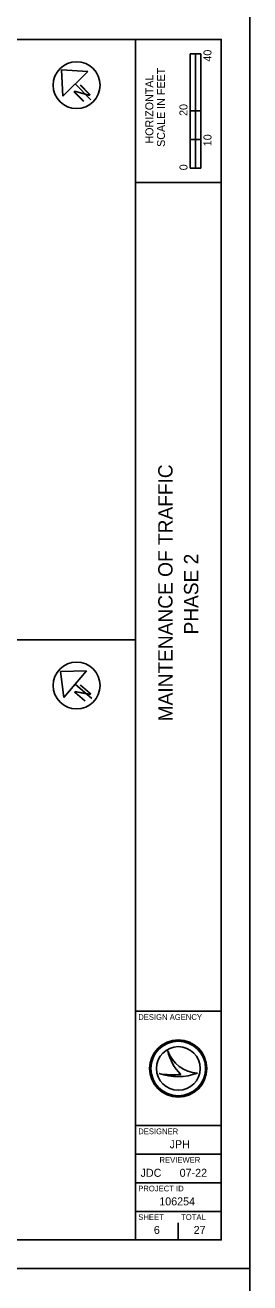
# Model space of a CAD drawing. Extents: x 0 to 5770, y -1320 to 440.
# Drawn here: x 601.5 to 680, y -445 to -5 of the extents above; entities that cross this region are included whole.
import ezdxf

# ---------------------------------------------------------------- set-up
doc = ezdxf.new("R2010")
doc.units = 0
for name, color, linetype in [('_CIVIL_CONSTRUCTION', 7, 'Continuous'), ('GE_P_Alignment', 7, 'Continuous'), ('GE_P_Alignment_100_Bearings', 7, 'Continuous'), ('GE_P_Alignment_100_Cardinal_Points', 7, 'Continuous'), ('HY_X_Water_Edge', 7, 'Continuous')]:
    doc.layers.add(name, color=color, linetype=linetype)

msp = doc.modelspace()

# ---------------------------------------------------------------- linework, layer by layer
at = {"layer": '_CIVIL_CONSTRUCTION'}
for points in [[(0, -440), (680, -440), (680, 0), (0, 0)], [(0, -880), (680, -880), (680, -440), (0, -440)]]:
    msp.add_lwpolyline(points, close=True, dxfattribs=at)
at = {"layer": 'GE_P_Alignment'}
for p, q in [((640, -430), (640, -10)), ((640, -60), (670, -60)), ((640, -350), (670, -350)), ((640, -390), (670, -390)), ((640, -400), (670, -400)), ((640, -410), (670, -410)), ((640, -420), (670, -420))]:
    msp.add_line(p, q, dxfattribs=at)
msp.add_lwpolyline([(30, -10), (670, -10), (670, -430), (30, -430)], close=True, dxfattribs=at)
at = {"layer": 'GE_P_Alignment_100_Bearings'}
for p, q in [((659.13, -55), (659.13, -15)), ((662.88, -15), (659.13, -15)), ((659.13, -35), (659.13, -15)), ((659.13, -15), (661, -15)), ((661, -15), (661.02, -15)), ((661.02, -15), (661.02, -35)), ((662.88, -15), (662.88, -55)), ((661.02, -35), (659.13, -35)), ((662.87, -35), (661, -35)), ((661, -35), (661, -45)), ((662.87, -45), (662.87, -35)), ((661, -45), (659.13, -45)), ((659.13, -45), (659.13, -55)), ((661, -55), (661, -45)), ((661, -45), (662.87, -45)), ((662.88, -55), (659.13, -55)), ((659.13, -55), (661, -55)), ((651.35, -363.81), (651.35, -363.81)), ((648.34, -371.81), (648.34, -371.81)), ((655, -370), (655, -370)), ((661.75, -371.63), (661.75, -371.63)), ((647.5, -426.5), (647.5, -426.5)), ((655, -430), (655, -424))]:
    msp.add_line(p, q, dxfattribs=at)
for radius in [10, 9.54, 9.54, 7.64]:
    msp.add_circle((655, -370), radius, dxfattribs=at)
for centre, radius, start, end in [((662.32, -360.05), 11.6, 198.9257, 198.9319), ((666.93, -360.6), 15.91, 191.6379, 191.6421), ((662.32, -360.05), 11.6, 198.9319, 267.1657), ((666.93, -360.6), 15.91, 191.6421, 226.0947), ((654.79, -352.6), 20.26, 251.4576, 290.0832), ((652.96, -346.91), 25.32, 259.4964, 259.4995), ((654.79, -352.6), 20.26, 251.4527, 251.4576), ((652.96, -346.91), 25.32, 259.4995, 276.6672)]:
    msp.add_arc(centre, radius, start, end, dxfattribs=at)
at = {"layer": 'GE_P_Alignment_100_Cardinal_Points'}
for p, q in [((614.24, -20.67), (614.62, -29.85)), ((623.41, -21.24), (614.24, -20.67)), ((614.62, -29.85), (623.41, -21.24)), ((619.01, -25.55), (624.43, -31.07)), ((30, -220), (640, -220)), ((622.98, -230.92), (613.79, -231.15)), ((613.79, -231.15), (614.97, -240.26)), ((614.97, -240.26), (622.98, -230.92)), ((618.97, -235.59), (624.85, -240.62))]:
    msp.add_line(p, q, dxfattribs=at)
for centre in [(619.47, -26.01), (619.47, -236.01)]:
    msp.add_circle(centre, 8.2, dxfattribs=at)
at = {"layer": 'HY_X_Water_Edge'}
for centre in [(619.47, -26.01), (619.47, -236.01)]:
    msp.add_circle(centre, 8.2, dxfattribs=at)

# ---------------------------------------------------------------- texts
at = {"layer": 'GE_P_Alignment_100_Bearings'}
for s, height, p in [('40', 2.8, (666.61, -17.75)), ('SCALE IN FEET', 2.8, (650.35, -47.59)), ('HORIZONTAL', 2.8, (646.3, -46.42)), ('20', 2.8, (658.21, -36.75)), ('10', 2.8, (666.61, -47.35)), ('0', 2.8, (658.21, -55.77)), ('MAINTENANCE OF TRAFFIC', 5, (653, -248.55)), ('PHASE 2', 5, (662, -218.17))]:
    msp.add_text(s, height=height, rotation=90, dxfattribs=at).set_placement(p)
for s, height, p in [('DESIGN AGENCY', 2, (641, -353)), ('DESIGNER', 2, (641, -393)), ('JPH', 2.8, (651.97, -397.9)), ('REVIEWER', 2, (648.44, -403)), ('JDC', 2.8, (641.82, -407.9)), ('07-22', 2.8, (655.48, -407.9)), ('PROJECT ID', 2, (641, -413)), ('106254', 2.8, (648.36, -417.9)), ('SHEET', 2, (641, -423)), ('TOTAL', 2, (656, -423)), ('6', 2.8, (646.47, -427.9)), ('27', 2.8, (660.37, -427.9))]:
    msp.add_text(s, height=height, dxfattribs=at).set_placement(p)
at = {"layer": 'GE_P_Alignment_100_Cardinal_Points'}
for rotation, p in [(44.4192, (621.38, -32.29)), (49.4056, (621.92, -242.1))]:
    msp.add_text('N', height=5, rotation=rotation, dxfattribs=at).set_placement(p)

doc.saveas('drawing.dxf')
